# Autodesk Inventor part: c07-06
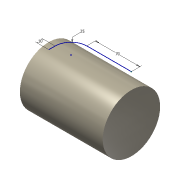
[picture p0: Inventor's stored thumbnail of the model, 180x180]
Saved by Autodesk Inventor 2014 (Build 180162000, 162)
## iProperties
Created: 2013-03
Part Number: c07-06
Material: Polycarbonate, Smoke
Document SubType Name: Modeling
Designer: Thom Tremblay
Density: 1.2 g/cm^3
Appearance: Light Beige
Author: Thom Tremblay
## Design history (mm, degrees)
sketch "Sketch1"
  geometry: C1 r 45 at (0, 0); 1 further point
  constraints: 1 centre point, 1 coincident
  dimensions: "d0" = 90 diameter of C1
extrude "Extrusion1" new body sketch "Sketch1" distance "d1" = 130; taper "d2" = 0 deg
workplane "Work Plane1"
sketch "Sketch2"
  geometry: L1 (0, 0)-(0, -70); L2 (25, -95)-(35, -95); A1 r 25 centre (25, -70) between (0, -70) and (25, -95); 1 further point
  constraints: 4 end point, 2 point on circle, 2 tangent, 1 centre point, 1 coincident, 1 perpendicular, 1 vertical
  dimensions: "d3" = 70 distance of L1.start L1.end; "d4" = 10 distance of L2.start L2.end; "d5" = 25 radius of A1
sketch "Profile"
  geometry: L1 (-10, 45)-(10, 45); L2 (10, 45)-(10, 35); L3 (10, 35)-(-10, 35); L4 (-10, 35)-(-10, 45); C1 r 45 at (0, 0) reference; 1 further point
  constraints: 8 end point, 2 parallel, 1 horizontal, 1 midpoint, 1 perpendicular, 1 tangent, 1 vertical alignment
  dimensions: "d7" = 10 distance of L1.end L2.end; "d8" = 20 distance of L2.end L3.end
body "Solid1"
